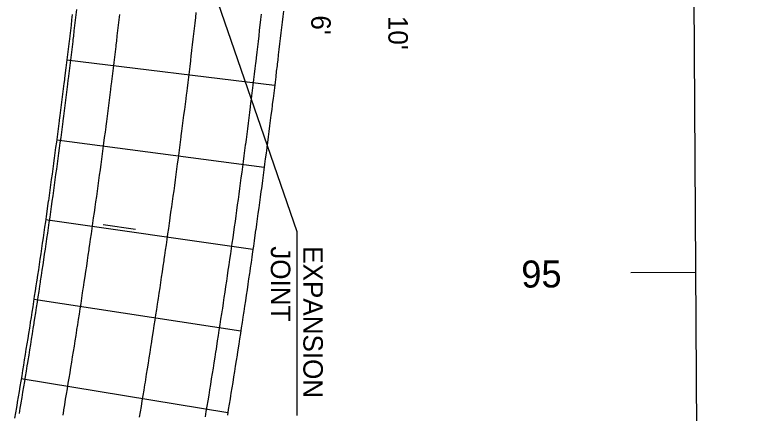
# Model space of a CAD drawing. Extents: x 2145147 to 2158018, y 137519 to 148068.
# Drawn here: x 2150689.7 to 2150824.7, y 144493.1 to 144566.8 of the extents above; entities that cross this region are included whole.
import ezdxf

# ---------------------------------------------------------------- set-up
doc = ezdxf.new("R2010")
doc.units = 0
for name, color, linetype in [('EX_Align', 7, 'Continuous'), ('EX_Align_Sta', 7, 'Continuous'), ('PR_Align_Ramp_B', 7, 'Continuous'), ('PR_Align_Service_C_Leader', 7, 'Continuous'), ('PR_Align_Service_C_Txt', 7, 'Continuous'), ('PR_Dimensions', 7, 'Continuous'), ('PR_Joint_Contraction', 7, 'Continuous'), ('PR_Joint_Long', 7, 'Continuous'), ('PR_Road_Concrete', 7, 'Continuous')]:
    doc.layers.add(name, color=color, linetype=linetype)

msp = doc.modelspace()

# ---------------------------------------------------------------- linework, layer by layer
at = {"layer": 'EX_Align'}
msp.add_line((2150824.67, 142998.65), (2150804.61, 146336.84), dxfattribs=at)
msp.add_lwpolyline([(2150803.53, 144519.11), (2150815.53, 144519.18)], dxfattribs=at)
at = {"layer": 'PR_Align_Ramp_B'}
msp.add_lwpolyline([(2150712.01, 144527.1), (2150706.07, 144527.94)], dxfattribs=at)
at = {"layer": 'PR_Align_Service_C_Leader'}
msp.add_lwpolyline([(2150721.76, 144585.05), (2150741.82, 144526.72), (2150741.82, 144492.69)], dxfattribs=at)
at = {"layer": 'PR_Joint_Contraction'}
for p, q in [((2150737.71, 144553.7), (2150699.33, 144558.37)), ((2150735.79, 144538.53), (2150697.46, 144543.6)), ((2150733.7, 144523.38), (2150695.42, 144528.85)), ((2150731.46, 144508.25), (2150693.24, 144514.12)), ((2150729.06, 144493.15), (2150690.9, 144499.42))]:
    msp.add_line(p, q, dxfattribs=at)
at = {"layer": 'PR_Joint_Long'}
for points in [[(2150709.06, 144566.85), (2150708.95, 144565.86), (2150708.83, 144564.87), (2150708.72, 144563.88), (2150708.6, 144562.89), (2150708.48, 144561.89), (2150708.41, 144561.24), (2150708.37, 144560.9), (2150708.25, 144559.91), (2150708.13, 144558.92), (2150708.01, 144557.93), (2150707.89, 144556.94), (2150707.83, 144556.44), (2150707.77, 144555.95), (2150707.64, 144554.95), (2150707.52, 144553.96), (2150707.49, 144553.71), (2150707.4, 144552.97), (2150707.27, 144551.98), (2150707.15, 144550.99), (2150707.02, 144550), (2150706.9, 144549.01), (2150706.77, 144548.02), (2150706.64, 144547.03), (2150706.53, 144546.17), (2150706.52, 144546.04), (2150706.39, 144545.05), (2150706.26, 144544.06), (2150706.13, 144543.07), (2150706, 144542.08), (2150705.86, 144541.09), (2150705.73, 144540.1), (2150705.6, 144539.11), (2150705.54, 144538.65), (2150705.47, 144538.12), (2150705.33, 144537.13), (2150705.2, 144536.14), (2150705.06, 144535.15), (2150704.92, 144534.16), (2150704.79, 144533.17), (2150704.65, 144532.18), (2150704.51, 144531.19), (2150704.5, 144531.13), (2150704.37, 144530.2), (2150704.23, 144529.22), (2150704.09, 144528.23), (2150703.95, 144527.24), (2150703.81, 144526.25), (2150703.66, 144525.26), (2150703.52, 144524.27), (2150703.43, 144523.61), (2150703.38, 144523.29), (2150703.23, 144522.3), (2150703.09, 144521.31), (2150702.94, 144520.32), (2150702.79, 144519.33), (2150702.65, 144518.35), (2150702.5, 144517.36), (2150702.35, 144516.37), (2150702.31, 144516.1), (2150702.2, 144515.38), (2150702.05, 144514.4), (2150701.9, 144513.41), (2150701.75, 144512.42), (2150701.59, 144511.44), (2150701.44, 144510.45), (2150701.29, 144509.46), (2150701.15, 144508.6), (2150701.13, 144508.48), (2150700.98, 144507.49), (2150700.82, 144506.5), (2150700.67, 144505.52), (2150700.51, 144504.53), (2150700.35, 144503.54), (2150700.19, 144502.56), (2150700.03, 144501.57), (2150699.96, 144501.1), (2150699.87, 144500.59), (2150699.71, 144499.6), (2150699.55, 144498.62), (2150699.39, 144497.63), (2150699.23, 144496.64), (2150699.06, 144495.66), (2150698.9, 144494.67), (2150698.74, 144493.69), (2150698.72, 144493.61), (2150698.57, 144492.7)], [(2150723.19, 144567.2), (2150723.09, 144566.26), (2150722.97, 144565.25), (2150722.86, 144564.25), (2150722.74, 144563.25), (2150722.62, 144562.25), (2150722.5, 144561.25), (2150722.39, 144560.25), (2150722.31, 144559.59), (2150722.27, 144559.24), (2150722.15, 144558.24), (2150722.03, 144557.24), (2150721.91, 144556.24), (2150721.78, 144555.24), (2150721.72, 144554.74), (2150721.66, 144554.24), (2150721.54, 144553.24), (2150721.42, 144552.24), (2150721.38, 144551.98), (2150721.29, 144551.24), (2150721.17, 144550.24), (2150721.04, 144549.24), (2150720.91, 144548.24), (2150720.79, 144547.24), (2150720.66, 144546.24), (2150720.53, 144545.24), (2150720.42, 144544.38), (2150720.4, 144544.23), (2150720.27, 144543.24), (2150720.14, 144542.24), (2150720.01, 144541.24), (2150719.87, 144540.24), (2150719.74, 144539.24), (2150719.61, 144538.24), (2150719.47, 144537.24), (2150719.41, 144536.77), (2150719.34, 144536.24), (2150719.2, 144535.24), (2150719.07, 144534.24), (2150718.93, 144533.24), (2150718.79, 144532.24), (2150718.65, 144531.24), (2150718.51, 144530.25), (2150718.37, 144529.25), (2150718.36, 144529.18), (2150718.23, 144528.25), (2150718.09, 144527.25), (2150717.95, 144526.25), (2150717.81, 144525.25), (2150717.66, 144524.25), (2150717.52, 144523.26), (2150717.38, 144522.26), (2150717.28, 144521.59), (2150717.23, 144521.26), (2150717.08, 144520.26), (2150716.94, 144519.27), (2150716.79, 144518.27), (2150716.64, 144517.27), (2150716.49, 144516.27), (2150716.34, 144515.28), (2150716.19, 144514.28), (2150716.15, 144514.01), (2150716.04, 144513.28), (2150715.89, 144512.29), (2150715.74, 144511.29), (2150715.58, 144510.29), (2150715.43, 144509.3), (2150715.28, 144508.3), (2150715.12, 144507.3), (2150714.98, 144506.43), (2150714.96, 144506.3), (2150714.81, 144505.31), (2150714.65, 144504.31), (2150714.49, 144503.32), (2150714.33, 144502.32), (2150714.17, 144501.33), (2150714.01, 144500.33), (2150713.85, 144499.34), (2150713.78, 144498.86), (2150713.69, 144498.34), (2150713.53, 144497.34), (2150713.37, 144496.35), (2150713.2, 144495.35), (2150713.04, 144494.36), (2150712.87, 144493.36), (2150712.71, 144492.37)], [(2150735.24, 144566.92), (2150735.12, 144565.91), (2150735.12, 144565.85), (2150735.01, 144564.9), (2150734.89, 144563.89), (2150734.78, 144562.88), (2150734.66, 144561.87), (2150734.54, 144560.86), (2150734.42, 144559.85), (2150734.3, 144558.84), (2150734.22, 144558.17), (2150734.18, 144557.83), (2150734.06, 144556.82), (2150733.94, 144555.81), (2150733.82, 144554.8), (2150733.7, 144553.79), (2150733.63, 144553.28), (2150733.57, 144552.78), (2150733.45, 144551.77), (2150733.32, 144550.76), (2150733.29, 144550.5), (2150733.2, 144549.75), (2150733.07, 144548.74), (2150732.95, 144547.73), (2150732.82, 144546.73), (2150732.69, 144545.72), (2150732.56, 144544.71), (2150732.43, 144543.7), (2150732.32, 144542.83), (2150732.3, 144542.69), (2150732.17, 144541.68), (2150732.04, 144540.68), (2150731.9, 144539.67), (2150731.77, 144538.66), (2150731.64, 144537.65), (2150731.5, 144536.64), (2150731.37, 144535.64), (2150731.3, 144535.17), (2150731.23, 144534.63), (2150731.09, 144533.62), (2150730.96, 144532.61), (2150730.82, 144531.61), (2150730.68, 144530.6), (2150730.54, 144529.59), (2150730.4, 144528.58), (2150730.26, 144527.58), (2150730.25, 144527.51), (2150730.12, 144526.57), (2150729.97, 144525.56), (2150729.83, 144524.56), (2150729.69, 144523.55), (2150729.54, 144522.54), (2150729.4, 144521.54), (2150729.25, 144520.53), (2150729.15, 144519.86), (2150729.1, 144519.53), (2150728.96, 144518.52), (2150728.81, 144517.51), (2150728.66, 144516.51), (2150728.51, 144515.5), (2150728.36, 144514.5), (2150728.21, 144513.49), (2150728.06, 144512.49), (2150728.02, 144512.21), (2150727.91, 144511.48), (2150727.75, 144510.48), (2150727.6, 144509.47), (2150727.44, 144508.47), (2150727.29, 144507.46), (2150727.13, 144506.46), (2150726.98, 144505.45), (2150726.84, 144504.57), (2150726.82, 144504.45), (2150726.66, 144503.44), (2150726.5, 144502.44), (2150726.34, 144501.43), (2150726.18, 144500.43), (2150726.02, 144499.43), (2150725.86, 144498.42), (2150725.7, 144497.42), (2150725.62, 144496.94), (2150725.54, 144496.41), (2150725.37, 144495.41), (2150725.21, 144494.41), (2150725.04, 144493.4), (2150724.88, 144492.4)]]:
    msp.add_lwpolyline(points, dxfattribs=at)
at = {"layer": 'PR_Road_Concrete'}
for points in [[(2150700.34, 144566.86), (2150700.22, 144565.87), (2150700.11, 144564.88), (2150699.99, 144563.9), (2150699.88, 144562.91), (2150699.8, 144562.27), (2150699.76, 144561.93), (2150699.64, 144560.94), (2150699.52, 144559.96), (2150699.4, 144558.97), (2150699.28, 144557.99), (2150699.22, 144557.49), (2150699.16, 144557), (2150699.04, 144556.02), (2150698.92, 144555.03), (2150698.89, 144554.78), (2150698.8, 144554.05), (2150698.68, 144553.06), (2150698.55, 144552.08), (2150698.43, 144551.09), (2150698.3, 144550.11), (2150698.18, 144549.12), (2150698.05, 144548.14), (2150697.94, 144547.29), (2150697.92, 144547.15), (2150697.79, 144546.17), (2150697.66, 144545.18), (2150697.53, 144544.2), (2150697.4, 144543.22), (2150697.27, 144542.23), (2150697.14, 144541.25), (2150697.01, 144540.26), (2150696.95, 144539.81), (2150696.88, 144539.28), (2150696.74, 144538.3), (2150696.61, 144537.31), (2150696.47, 144536.33), (2150696.34, 144535.35), (2150696.2, 144534.36), (2150696.07, 144533.38), (2150695.93, 144532.4), (2150695.92, 144532.33), (2150695.79, 144531.42), (2150695.65, 144530.43), (2150695.51, 144529.45), (2150695.37, 144528.47), (2150695.23, 144527.49), (2150695.09, 144526.5), (2150694.94, 144525.52), (2150694.85, 144524.86), (2150694.8, 144524.54), (2150694.66, 144523.56), (2150694.51, 144522.57), (2150694.37, 144521.59), (2150694.22, 144520.61), (2150694.08, 144519.63), (2150693.93, 144518.65), (2150693.78, 144517.67), (2150693.74, 144517.4), (2150693.63, 144516.68), (2150693.48, 144515.7), (2150693.33, 144514.72), (2150693.18, 144513.74), (2150693.03, 144512.76), (2150692.88, 144511.78), (2150692.73, 144510.8), (2150692.59, 144509.94), (2150692.57, 144509.82), (2150692.42, 144508.84), (2150692.26, 144507.86), (2150692.11, 144506.88), (2150691.95, 144505.9), (2150691.79, 144504.92), (2150691.64, 144503.94), (2150691.48, 144502.96), (2150691.4, 144502.49), (2150691.32, 144501.98), (2150691.16, 144501), (2150691, 144500.02), (2150690.84, 144499.04), (2150690.68, 144498.06), (2150690.51, 144497.08), (2150690.35, 144496.1), (2150690.19, 144495.12), (2150690.17, 144495.04), (2150690.02, 144494.14), (2150689.86, 144493.16), (2150689.69, 144492.19)], [(2150701.11, 144567.77), (2150701, 144566.78), (2150700.89, 144565.79), (2150700.77, 144564.81), (2150700.66, 144563.82), (2150700.54, 144562.83), (2150700.46, 144562.19), (2150700.42, 144561.85), (2150700.3, 144560.86), (2150700.19, 144559.88), (2150700.07, 144558.89), (2150699.95, 144557.9), (2150699.89, 144557.41), (2150699.83, 144556.92), (2150699.7, 144555.93), (2150699.58, 144554.95), (2150699.55, 144554.69), (2150699.46, 144553.96), (2150699.34, 144552.98), (2150699.21, 144551.99), (2150699.09, 144551.01), (2150698.96, 144550.02), (2150698.84, 144549.04), (2150698.71, 144548.05), (2150698.6, 144547.2), (2150698.58, 144547.07), (2150698.45, 144546.08), (2150698.33, 144545.1), (2150698.2, 144544.11), (2150698.07, 144543.13), (2150697.93, 144542.14), (2150697.8, 144541.16), (2150697.67, 144540.18), (2150697.61, 144539.72), (2150697.54, 144539.19), (2150697.4, 144538.21), (2150697.27, 144537.22), (2150697.14, 144536.24), (2150697, 144535.26), (2150696.86, 144534.27), (2150696.73, 144533.29), (2150696.59, 144532.31), (2150696.58, 144532.24), (2150696.45, 144531.32), (2150696.31, 144530.34), (2150696.17, 144529.36), (2150696.03, 144528.37), (2150695.89, 144527.39), (2150695.75, 144526.41), (2150695.6, 144525.42), (2150695.51, 144524.77), (2150695.46, 144524.44), (2150695.32, 144523.46), (2150695.17, 144522.48), (2150695.03, 144521.49), (2150694.88, 144520.51), (2150694.73, 144519.53), (2150694.59, 144518.55), (2150694.44, 144517.57), (2150694.4, 144517.3), (2150694.29, 144516.58), (2150694.14, 144515.6), (2150693.99, 144514.62), (2150693.84, 144513.64), (2150693.69, 144512.66), (2150693.54, 144511.68), (2150693.38, 144510.7), (2150693.25, 144509.84), (2150693.23, 144509.71), (2150693.08, 144508.73), (2150692.92, 144507.75), (2150692.77, 144506.77), (2150692.61, 144505.79), (2150692.45, 144504.81), (2150692.29, 144503.83), (2150692.14, 144502.85), (2150692.06, 144502.38), (2150691.98, 144501.87), (2150691.82, 144500.89), (2150691.66, 144499.91), (2150691.5, 144498.93), (2150691.33, 144497.95), (2150691.17, 144496.97), (2150691.01, 144495.99), (2150690.85, 144495.01), (2150690.83, 144494.93), (2150690.68, 144494.03), (2150690.52, 144493.05)], [(2150739.33, 144567.48), (2150739.21, 144566.47), (2150739.1, 144565.45), (2150739.09, 144565.4), (2150738.98, 144564.44), (2150738.87, 144563.43), (2150738.75, 144562.42), (2150738.63, 144561.4), (2150738.51, 144560.39), (2150738.39, 144559.38), (2150738.28, 144558.37), (2150738.2, 144557.7), (2150738.16, 144557.35), (2150738.03, 144556.34), (2150737.91, 144555.33), (2150737.79, 144554.32), (2150737.67, 144553.3), (2150737.61, 144552.8), (2150737.54, 144552.29), (2150737.42, 144551.28), (2150737.29, 144550.27), (2150737.26, 144550.01), (2150737.17, 144549.26), (2150737.04, 144548.24), (2150736.91, 144547.23), (2150736.79, 144546.22), (2150736.66, 144545.21), (2150736.53, 144544.2), (2150736.4, 144543.19), (2150736.28, 144542.32), (2150736.27, 144542.18), (2150736.13, 144541.17), (2150736, 144540.15), (2150735.87, 144539.14), (2150735.74, 144538.13), (2150735.6, 144537.12), (2150735.47, 144536.11), (2150735.33, 144535.1), (2150735.27, 144534.63), (2150735.19, 144534.09), (2150735.06, 144533.08), (2150734.92, 144532.07), (2150734.78, 144531.06), (2150734.64, 144530.05), (2150734.5, 144529.04), (2150734.36, 144528.03), (2150734.22, 144527.02), (2150734.21, 144526.95), (2150734.08, 144526.01), (2150733.93, 144525), (2150733.79, 144523.99), (2150733.65, 144522.98), (2150733.5, 144521.97), (2150733.36, 144520.97), (2150733.21, 144519.96), (2150733.11, 144519.28), (2150733.06, 144518.95), (2150732.91, 144517.94), (2150732.77, 144516.93), (2150732.62, 144515.92), (2150732.47, 144514.91), (2150732.32, 144513.9), (2150732.16, 144512.9), (2150732.01, 144511.89), (2150731.97, 144511.61), (2150731.86, 144510.88), (2150731.71, 144509.87), (2150731.55, 144508.86), (2150731.4, 144507.86), (2150731.24, 144506.85), (2150731.09, 144505.84), (2150730.93, 144504.83), (2150730.79, 144503.95), (2150730.77, 144503.83), (2150730.61, 144502.82), (2150730.45, 144501.81), (2150730.29, 144500.81), (2150730.13, 144499.8), (2150729.97, 144498.79), (2150729.81, 144497.79), (2150729.65, 144496.78), (2150729.57, 144496.3), (2150729.49, 144495.77), (2150729.32, 144494.77), (2150729.16, 144493.76), (2150728.99, 144492.75)]]:
    msp.add_lwpolyline(points, dxfattribs=at)

# ---------------------------------------------------------------- texts
at = {"layer": 'EX_Align_Sta'}
msp.add_text('95', height=5, rotation=0.3443, dxfattribs=at).set_placement((2150783.29, 144516.32))
at = {"layer": 'PR_Align_Service_C_Txt'}
for s, p in [('JOINT', (2150737.02, 144523.97)), ('EXPANSION', (2150743.02, 144523.97))]:
    msp.add_text(s, height=3.6, rotation=270, dxfattribs=at).set_placement(p)
at = {"layer": 'PR_Dimensions'}
for s, p in [("6'", (2150744.48, 144566.68)), ("10'", (2150758.72, 144566.58))]:
    msp.add_text(s, height=3.6, rotation=269.9996, dxfattribs=at).set_placement(p)

doc.saveas('drawing.dxf')
